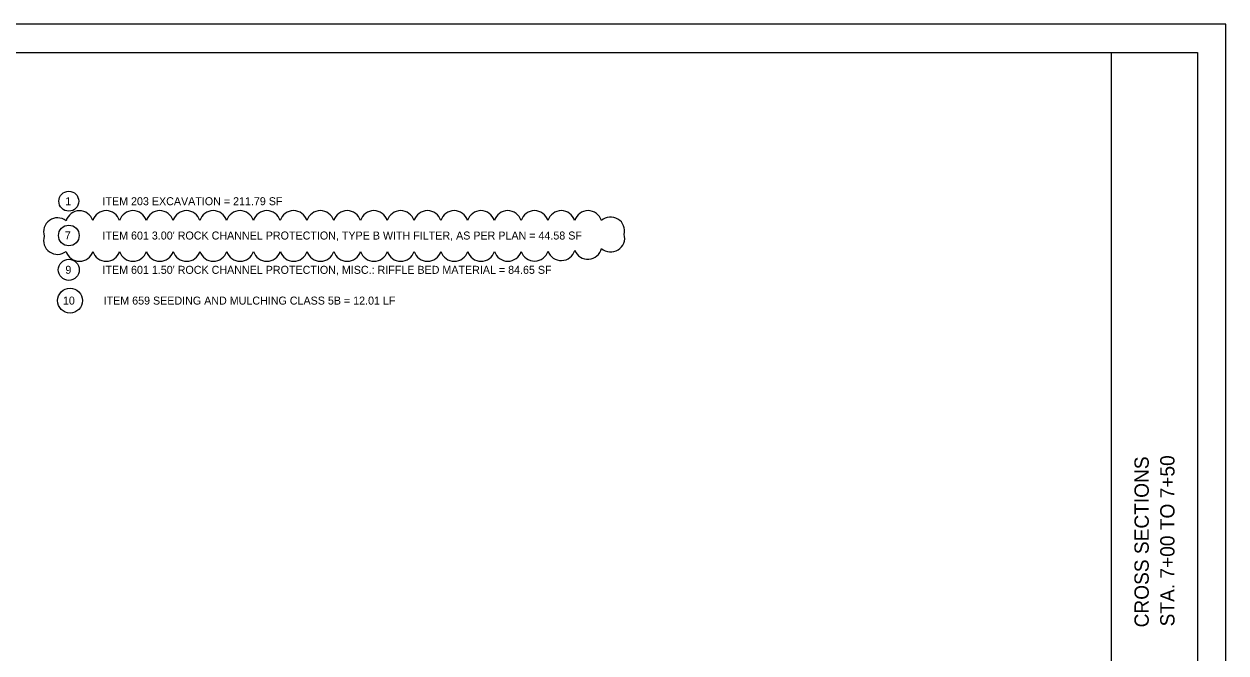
# Model space of a CAD drawing. Extents: x -179 to 34, y 0 to 22.
# Drawn here: x 12.98 to 34, y 11 to 22 of the extents above; entities that cross this region are included whole.
import ezdxf

# ---------------------------------------------------------------- set-up
doc = ezdxf.new("R2010")
doc.units = 0
for name, color, linetype in [('CS-ALGN-TEXT', 7, 'Continuous'), ('CS-ANNO', 7, 'Continuous'), ('CS-ANNO-MATC', 7, 'Continuous'), ('CS-ANNO-MATC-TEXT', 7, 'Continuous')]:
    doc.layers.add(name, color=color, linetype=linetype)

msp = doc.modelspace()

# ---------------------------------------------------------------- linework, layer by layer
at = {"layer": 'CS-ALGN-TEXT'}
for centre, radius, start, end in [((13.949, 18.489), 0.245, 18.0505, 163.0505), ((14.416, 18.491), 0.245, 17.5, 162.5), ((14.885, 18.491), 0.245, 17.5, 162.5), ((15.353, 18.491), 0.245, 17.5, 162.5), ((15.821, 18.491), 0.245, 17.5, 162.5), ((16.289, 18.491), 0.245, 17.5, 162.5), ((16.757, 18.491), 0.245, 17.5, 162.5), ((17.226, 18.491), 0.245, 17.5, 162.5), ((17.694, 18.491), 0.245, 17.5, 162.5), ((18.162, 18.491), 0.245, 17.5, 162.5), ((18.63, 18.491), 0.245, 17.5, 162.5), ((19.098, 18.491), 0.245, 17.5, 162.5), ((19.567, 18.491), 0.245, 17.5, 162.5), ((20.035, 18.491), 0.245, 17.5, 162.5), ((20.503, 18.491), 0.245, 17.5, 162.5), ((20.971, 18.491), 0.245, 17.5, 162.5), ((21.439, 18.491), 0.245, 17.5, 162.5), ((21.908, 18.491), 0.245, 17.5, 162.5), ((22.376, 18.491), 0.245, 17.5, 162.5), ((22.844, 18.491), 0.245, 17.5, 162.5), ((13.566, 18.365), 0.245, 52.7464, 197.7464), ((23.239, 18.38), 0.245, 346.0355, 131.0355), ((13.566, 18.217), 0.245, 162.6307, 307.6307), ((23.239, 18.26), 0.246, 229.2277, 14.2277), ((13.95, 18.096), 0.245, 197.5, 342.5), ((14.418, 18.096), 0.245, 197.5, 342.5), ((14.886, 18.096), 0.245, 197.5, 342.5), ((15.355, 18.096), 0.245, 197.5, 342.5), ((15.823, 18.096), 0.245, 197.5, 342.5), ((16.291, 18.096), 0.245, 197.5, 342.5), ((16.759, 18.096), 0.245, 197.5, 342.5), ((17.227, 18.096), 0.245, 197.5, 342.5), ((17.696, 18.096), 0.245, 197.5, 342.5), ((18.164, 18.096), 0.245, 197.5, 342.5), ((18.632, 18.096), 0.245, 197.5, 342.5), ((19.1, 18.096), 0.245, 197.5, 342.5), ((19.568, 18.096), 0.245, 197.5, 342.5), ((20.037, 18.096), 0.245, 197.5, 342.5), ((20.505, 18.096), 0.245, 197.5, 342.5), ((20.973, 18.096), 0.245, 197.5, 342.5), ((21.441, 18.097), 0.245, 197.6271, 342.6271), ((21.909, 18.1), 0.245, 198.1381, 343.1381), ((22.375, 18.109), 0.245, 199.0512, 344.0512), ((22.84, 18.132), 0.245, 201.5234, 346.5234)]:
    msp.add_arc(centre, radius, start, end, dxfattribs=at)
at = {"layer": 'CS-ANNO'}
msp.add_lwpolyline([(0, 0), (34, 0), (34, 22), (0, 22)], close=True, dxfattribs=at)
at = {"layer": 'CS-ANNO-MATC'}
msp.add_line((32, 0.5), (32, 21.5), dxfattribs=at)
msp.add_lwpolyline([(1.5, 21.5), (33.5, 21.5), (33.5, 0.5), (1.5, 0.5)], close=True, dxfattribs=at)
at = {"layer": 'CS-ANNO-MATC-TEXT'}
for centre, radius in [((13.763, 18.901), 0.174), ((13.763, 18.301), 0.181), ((13.763, 17.701), 0.184), ((13.784, 17.162), 0.218)]:
    msp.add_circle(centre, radius, dxfattribs=at)

# ---------------------------------------------------------------- texts
at = {"layer": 'CS-ALGN-TEXT'}
for s, p in [('CROSS SECTIONS', (32.65, 11.447)), ('STA. 7+00 TO 7+50', (33.1, 11.465))]:
    msp.add_text(s, height=0.25, rotation=90, dxfattribs=at).set_placement(p)
at = {"layer": 'CS-ANNO-MATC-TEXT'}
for s, p in [('1', (13.702, 18.831)), ('ITEM 203 EXCAVATION = 211.79 SF', (14.352, 18.831)), ('7', (13.693, 18.232)), ("ITEM 601 3.00' ROCK CHANNEL PROTECTION, TYPE B WITH FILTER, AS PER PLAN = 44.58 SF", (14.352, 18.231)), ('9', (13.703, 17.632)), ("ITEM 601 1.50' ROCK CHANNEL PROTECTION, MISC.: RIFFLE BED MATERIAL = 84.65 SF", (14.352, 17.631)), ('10', (13.66, 17.093)), ('ITEM 659 SEEDING AND MULCHING CLASS 5B = 12.01 LF', (14.372, 17.093))]:
    msp.add_text(s, height=0.14, dxfattribs=at).set_placement(p)

doc.saveas('drawing.dxf')
